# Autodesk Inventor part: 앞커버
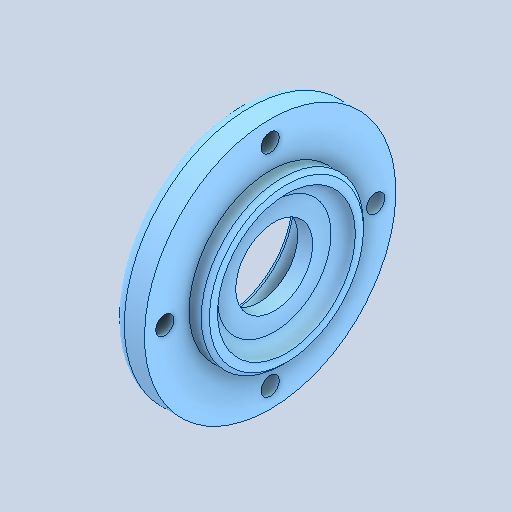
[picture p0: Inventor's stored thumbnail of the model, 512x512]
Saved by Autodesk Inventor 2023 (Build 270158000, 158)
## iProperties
Created: 2024-09
Part Number: 앞커버
Material: 알루미늄 6061
Document SubType Name: Modeling
Designer: asung
Density: 2.7 g/cm^3
Appearance: 기본값
Author: jhkim
Sending System: Autodesk Inventor 2025
Preprocessor: ST-DEVELOPER v20
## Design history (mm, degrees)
feature "솔리드1"
node "솔리드2"
